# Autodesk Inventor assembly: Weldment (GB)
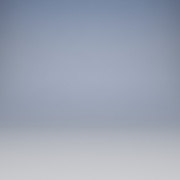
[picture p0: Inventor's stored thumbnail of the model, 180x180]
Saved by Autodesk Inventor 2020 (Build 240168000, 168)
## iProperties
Length Units: 11269
Angle Units: 11283
Time Units: 11279
Mass Units: 11290
Length Display Precision: 3
Angle Display Precision: 2
Part Number: Weldment (GB)
Document SubType Name: Weldment
Created: 2002-06
Designer: smithga
Created: 2002-08
Designer: F.Stasiak
Weld Material: Welded Aluminum-6061
Catalog Web Link: www.expertbooks.pl
Manager: www.cadconsulting.pl
Company: Fabian Stasiak CAD Consulting
Control State: 0
Master: False
Shininess: 64.0
Angle Units: 11279
Time Units: 11290
Mass Units: 11283
Compacted: True
Density: 0.0
Volumn: 0.0
Area: 0.0
PropertySet Name: Model Information
Author: F.Stasiak
Subject: Zbiór ćwiczeń. Autodesk Inventor 2020. Kurs Professional
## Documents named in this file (1)
- M:\AUTOBUILD\M24_168_RTM\Application\App\Templates\en-US\Metric\Weldment (GB).iam
